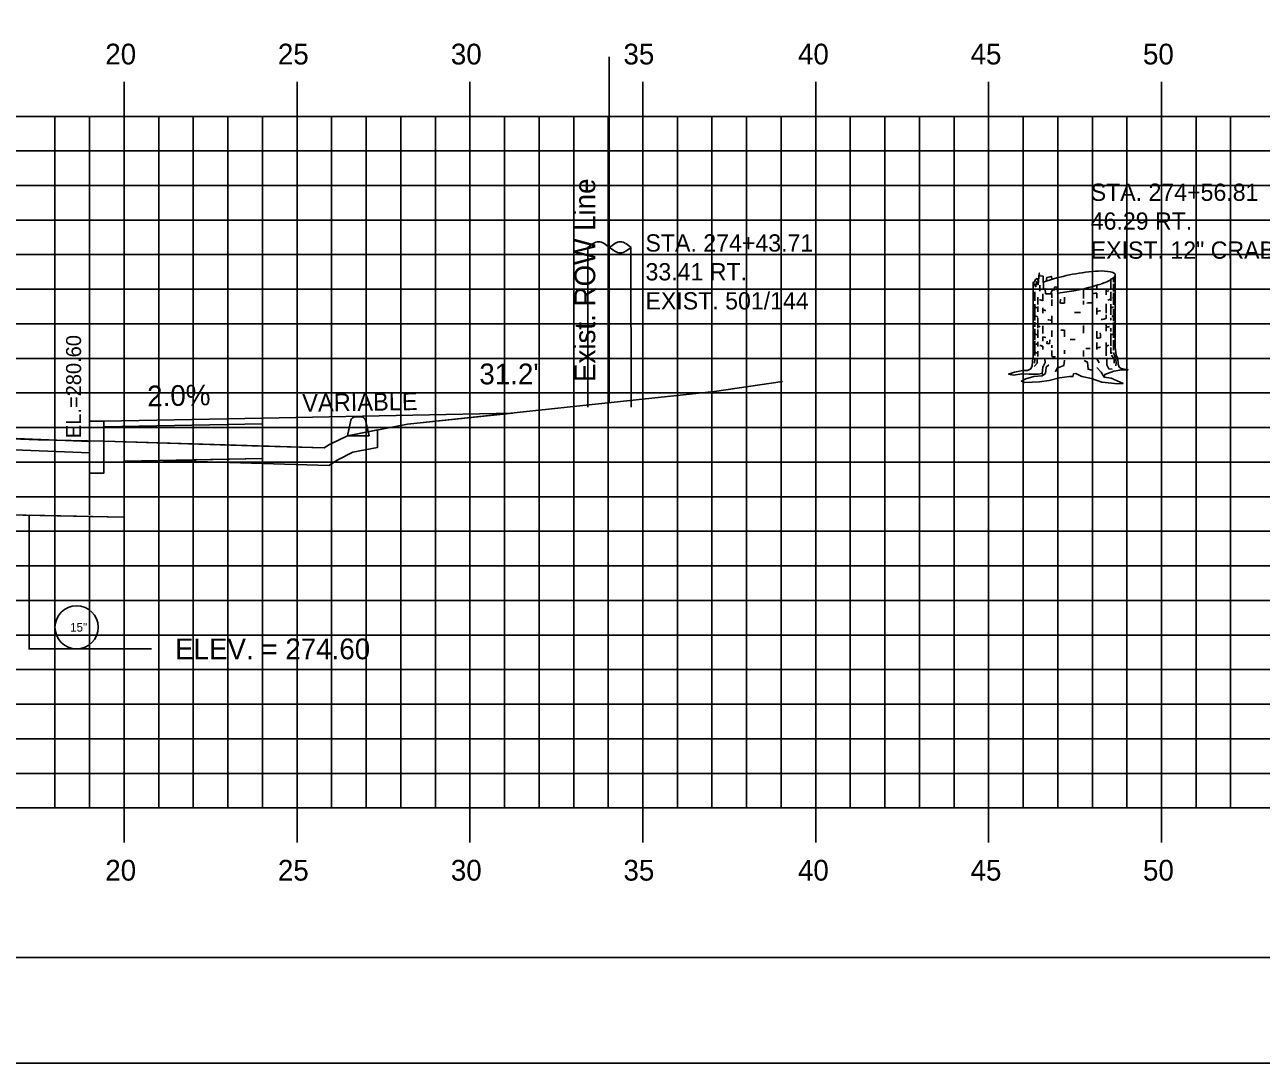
# Model space of a CAD drawing. Extents: x 853340 to 853510, y 366268 to 366378.
# Drawn here: x 853440.22 to 853475.99, y 366268.18 to 366298.21 of the extents above; entities that cross this region are included whole.
import ezdxf

# ---------------------------------------------------------------- set-up
doc = ezdxf.new("R2010")
doc.units = 0
for name, color, linetype in [('ANNOTATION', 7, 'Continuous'), ('BORDER', 7, 'Continuous'), ('D_Curb_Type_1_Rt', 7, 'Continuous'), ('D_Roadway_Edge_TW', 7, 'Continuous'), ('D_Roadway_FinishedGrade', 7, 'Continuous'), ('D_Roadway_Sidewalks_Paved', 7, 'Continuous'), ('D_Roadway_SubGrade', 7, 'Continuous'), ('D_Text_Monospaced', 7, 'Continuous'), ('D_Text_Standard', 7, 'Continuous'), ('E_ROW_Line', 7, 'Continuous'), ('H_V ANNOTATION', 7, 'Continuous'), ('JUNK COM EXC', 7, 'Continuous'), ('JUNK FILL', 7, 'Continuous'), ('junk grubnfill', 7, 'Continuous'), ('junk strct exc', 7, 'Continuous'), ('MAJOR', 7, 'Continuous'), ('MINOR', 7, 'Continuous'), ('PDRAIN', 7, 'Continuous'), ('PLOT BOUNDARY', 7, 'Continuous'), ('S_Curb_Type_3', 7, 'Continuous'), ('S_Roadway_Centerline', 7, 'Continuous'), ('S_Trees_Decid_Pay', 7, 'Continuous'), ('S_Utilities_Pole_Power', 7, 'Continuous')]:
    doc.layers.add(name, color=color, linetype=linetype)

msp = doc.modelspace()

# ---------------------------------------------------------------- linework, layer by layer
at = {"layer": 'BORDER'}
msp.add_line((853348.1, 366271.236), (853508.1, 366271.236), dxfattribs=at)
at = {"layer": 'D_Curb_Type_1_Rt'}
msp.add_lwpolyline([(853442.517, 366286.744), (853442.517, 366285.244), (853442.1, 366285.244), (853442.1, 366286.744)], close=True, dxfattribs=at)
at = {"layer": 'D_Roadway_Edge_TW'}
msp.add_lwpolyline([(853404.1, 366286.267), (853412.1, 366286.587), (853423.1, 366286.701), (853434.1, 366286.48), (853442.1, 366286.16)], dxfattribs=at)
at = {"layer": 'D_Roadway_FinishedGrade'}
msp.add_line((853447.105, 366286.835), (853454.338, 366286.979), dxfattribs=at)
at = {"layer": 'D_Roadway_Sidewalks_Paved'}
msp.add_lwpolyline([(853442.517, 366286.744), (853447.105, 366286.835), (853447.105, 366286.669), (853442.517, 366286.577)], close=True, dxfattribs=at)
at = {"layer": 'D_Roadway_SubGrade'}
msp.add_line((853450.424, 366286.489), (853450.424, 366285.98), dxfattribs=at)
for points in [[(853442.516, 366286.577), (853447.105, 366286.669), (853447.105, 366285.669), (853443.1, 366285.588), (853443.1, 366283.968)], [(853443.1, 366283.968), (853434.108, 366284.148), (853434.108, 366286.148), (853442.1, 366285.828)], [(853444.225, 366285.611), (853449.017, 366285.467), (853449.284, 366285.631), (853449.718, 366285.846), (853450.424, 366285.98)]]:
    msp.add_lwpolyline(points, dxfattribs=at)
at = {"layer": 'D_Text_Standard'}
msp.add_lwpolyline([(853443.1, 366280.159), (853443.212, 366280.159), (853443.892, 366280.159)], dxfattribs=at)
at = {"layer": 'E_ROW_Line'}
msp.add_line((853457.124, 366287.276), (853457.124, 366297.276), dxfattribs=at)
at = {"layer": 'JUNK COM EXC'}
msp.add_lwpolyline([(853403.1, 366285.982), (853403.1, 366284.074), (853412.108, 366284.254), (853423.108, 366284.368), (853443.1, 366283.968), (853443.1, 366285.588), (853447.105, 366285.669), (853447.105, 366286.025), (853442.522, 366286.163), (853440.609, 366286.208), (853435.982, 366286.375), (853424.096, 366286.691), (853423.104, 366286.714), (853422.159, 366286.693), (853411.503, 366286.496), (853410.582, 366286.432), (853404.575, 366286.053), (853403.1, 366285.982)], dxfattribs=at)
at = {"layer": 'JUNK FILL'}
msp.add_lwpolyline([(853447.105, 366286.025), (853448.883, 366285.971), (853449.042, 366286.069), (853449.557, 366286.324), (853451.29, 366286.654), (853454.338, 366286.979), (853447.105, 366286.835), (853447.105, 366286.669), (853447.105, 366286.025)], dxfattribs=at)
at = {"layer": 'junk grubnfill'}
msp.add_lwpolyline([(853447.105, 366286.025), (853447.105, 366285.669), (853444.225, 366285.611), (853449.017, 366285.467), (853449.284, 366285.631), (853449.718, 366285.846), (853450.424, 366285.98), (853450.424, 366286.489), (853449.557, 366286.324), (853449.042, 366286.069), (853448.883, 366285.971), (853447.105, 366286.025)], dxfattribs=at)
at = {"layer": 'junk strct exc'}
msp.add_lwpolyline([(853440.35, 366284.023), (853440.35, 366280.159), (853443.1, 366280.159), (853443.1, 366283.968)], close=True, dxfattribs=at)
at = {"layer": 'MAJOR'}
for p, q in [((853443.1, 366296.561), (853443.1, 366295.559)), ((853448.1, 366296.561), (853448.1, 366295.559)), ((853453.1, 366296.561), (853453.1, 366295.559)), ((853458.1, 366296.561), (853458.1, 366295.559)), ((853463.1, 366296.561), (853463.1, 366295.559)), ((853468.1, 366296.561), (853468.1, 366295.559)), ((853473.1, 366296.561), (853473.1, 366295.559)), ((853353.1, 366295.559), (853493.1, 366295.559)), ((853353.1, 366295.559), (853493.1, 366295.559)), ((853443.1, 366275.559), (853443.1, 366295.559)), ((853448.1, 366275.559), (853448.1, 366295.559)), ((853453.1, 366275.559), (853453.1, 366295.559)), ((853458.1, 366275.559), (853458.1, 366295.559)), ((853463.1, 366275.559), (853463.1, 366295.559)), ((853468.1, 366275.559), (853468.1, 366295.559)), ((853473.1, 366275.559), (853473.1, 366295.559)), ((853353.1, 366290.559), (853493.1, 366290.559)), ((853353.1, 366285.559), (853493.1, 366285.559)), ((853353.1, 366280.559), (853493.1, 366280.559)), ((853353.1, 366275.559), (853493.1, 366275.559)), ((853353.1, 366275.559), (853493.1, 366275.559)), ((853443.1, 366274.557), (853443.1, 366275.559)), ((853448.1, 366274.557), (853448.1, 366275.559)), ((853453.1, 366274.557), (853453.1, 366275.559)), ((853458.1, 366274.557), (853458.1, 366275.559)), ((853463.1, 366274.557), (853463.1, 366275.559)), ((853468.1, 366274.557), (853468.1, 366275.559)), ((853473.1, 366274.557), (853473.1, 366275.559))]:
    msp.add_line(p, q, dxfattribs=at)
at = {"layer": 'MINOR'}
for p, q in [((853441.1, 366275.559), (853441.1, 366295.559)), ((853442.1, 366284.032), (853442.1, 366295.559)), ((853444.1, 366275.559), (853444.1, 366295.559)), ((853445.1, 366275.559), (853445.1, 366295.559)), ((853446.1, 366275.559), (853446.1, 366295.559)), ((853447.1, 366275.559), (853447.1, 366295.559)), ((853449.1, 366275.559), (853449.1, 366295.559)), ((853450.1, 366275.559), (853450.1, 366295.559)), ((853451.1, 366275.559), (853451.1, 366295.559)), ((853452.1, 366275.559), (853452.1, 366295.559)), ((853454.1, 366275.559), (853454.1, 366295.559)), ((853455.1, 366275.559), (853455.1, 366295.559)), ((853456.1, 366275.559), (853456.1, 366295.559)), ((853457.1, 366275.559), (853457.1, 366295.559)), ((853459.1, 366275.559), (853459.1, 366295.559)), ((853460.1, 366275.559), (853460.1, 366295.559)), ((853461.1, 366275.559), (853461.1, 366295.559)), ((853462.1, 366275.559), (853462.1, 366295.559)), ((853464.1, 366275.559), (853464.1, 366295.559)), ((853465.1, 366275.559), (853465.1, 366295.559)), ((853466.1, 366275.559), (853466.1, 366295.559)), ((853467.1, 366275.559), (853467.1, 366295.559)), ((853469.1, 366275.559), (853469.1, 366295.559)), ((853470.1, 366275.559), (853470.1, 366295.559)), ((853471.1, 366275.559), (853471.1, 366295.559)), ((853472.1, 366275.559), (853472.1, 366295.559)), ((853474.1, 366275.559), (853474.1, 366295.559)), ((853475.1, 366275.559), (853475.1, 366295.559)), ((853353.1, 366294.559), (853493.1, 366294.559)), ((853353.1, 366293.559), (853493.1, 366293.559)), ((853353.1, 366292.559), (853493.1, 366292.559)), ((853353.1, 366291.559), (853493.1, 366291.559)), ((853353.1, 366289.559), (853493.1, 366289.559)), ((853353.1, 366288.559), (853493.1, 366288.559)), ((853353.1, 366287.559), (853493.1, 366287.559)), ((853353.1, 366286.559), (853493.1, 366286.559)), ((853353.1, 366284.559), (853493.1, 366284.559)), ((853442.1, 366275.559), (853442.1, 366283.988)), ((853353.1, 366283.559), (853493.1, 366283.559)), ((853353.1, 366282.559), (853493.1, 366282.559)), ((853353.1, 366281.559), (853493.1, 366281.559)), ((853353.1, 366279.559), (853493.1, 366279.559)), ((853353.1, 366278.559), (853493.1, 366278.559)), ((853353.1, 366277.559), (853493.1, 366277.559)), ((853353.1, 366276.559), (853493.1, 366276.559))]:
    msp.add_line(p, q, dxfattribs=at)
at = {"layer": 'PDRAIN'}
msp.add_lwpolyline([(853440.35, 366284.023), (853440.35, 366280.159), (853443.1, 366280.159), (853443.1, 366283.968)], dxfattribs=at)
msp.add_circle((853441.725, 366280.784), 0.625, dxfattribs=at)
at = {"layer": 'PLOT BOUNDARY'}
msp.add_lwpolyline([(853340.007, 366268.177), (853510.007, 366268.177), (853510.007, 366378.177), (853340.007, 366378.177)], close=True, dxfattribs=at)
at = {"layer": 'S_Curb_Type_3'}
for points in [[(853450.079, 366286.769), (853450.182, 366286.324), (853449.557, 366286.324), (853449.66, 366286.769)], [(853449.781, 366286.866), (853449.957, 366286.866)]]:
    msp.add_lwpolyline(points, dxfattribs=at)
for centre, start, end in [((853449.781, 366286.741), 90, 167.0054), ((853449.957, 366286.741), 12.9946, 90)]:
    msp.add_arc(centre, 0.125, start, end, dxfattribs=at)
at = {"layer": 'S_Roadway_Centerline'}
msp.add_lwpolyline([(853378.002, 366284.035), (853391.663, 366284.218), (853393.728, 366284.501), (853401.276, 366285.894), (853404.575, 366286.053), (853410.582, 366286.432), (853411.503, 366286.496), (853422.159, 366286.693), (853423.104, 366286.714), (853424.096, 366286.691), (853435.982, 366286.375), (853440.609, 366286.208), (853442.522, 366286.163), (853448.883, 366285.971), (853449.042, 366286.069), (853449.557, 366286.324), (853451.29, 366286.654), (853460.175, 366287.602), (853462.142, 366287.892)], dxfattribs=at)
at = {"layer": 'S_Trees_Decid_Pay'}
for p, q in [((853469.586, 366290.68), (853469.586, 366290.505)), ((853471.226, 366290.672), (853471.226, 366290.585)), ((853471.631, 366290.839), (853471.631, 366290.585)), ((853471.711, 366290.883), (853471.711, 366290.762)), ((853471.711, 366290.711), (853471.711, 366290.497)), ((853469.437, 366290.48), (853469.437, 366290.225)), ((853469.523, 366290.334), (853469.523, 366290.122)), ((853469.671, 366290.431), (853469.671, 366290.226)), ((853469.932, 366290.433), (853469.932, 366290.314)), ((853469.932, 366290.262), (853469.932, 366290.077)), ((853470.17, 366290.161), (853470.176, 366290.268)), ((853470.297, 366290.334), (853470.297, 366290.154)), ((853470.843, 366290.571), (853470.843, 366290.291)), ((853471.226, 366290.444), (853471.226, 366290.305)), ((853471.498, 366290.585), (853471.498, 366290.394)), ((853471.631, 366290.489), (853471.631, 366290.225)), ((853471.711, 366290.451), (853471.711, 366290.113)), ((853469.437, 366290.128), (853469.437, 366289.659)), ((853469.523, 366290.056), (853469.523, 366289.908)), ((853469.671, 366290.019), (853469.671, 366289.865)), ((853470.843, 366290.225), (853470.843, 366290.122)), ((853471.226, 366290.019), (853471.226, 366289.827)), ((853471.498, 366290.142), (853471.498, 366289.865)), ((853471.631, 366290.128), (853471.631, 366289.819)), ((853471.711, 366289.997), (853471.711, 366289.636)), ((853469.437, 366289.608), (853469.437, 366289.474)), ((853469.523, 366289.731), (853469.523, 366289.43)), ((853469.932, 366289.791), (853469.932, 366289.562)), ((853471.498, 366289.819), (853471.498, 366289.711)), ((853471.498, 366289.576), (853471.498, 366289.348)), ((853471.631, 366289.731), (853471.631, 366289.665)), ((853471.711, 366289.599), (853471.711, 366289.15)), ((853469.437, 366289.416), (853469.437, 366289.09)), ((853469.523, 366289.393), (853469.523, 366289.15)), ((853469.671, 366289.502), (853469.671, 366289.282)), ((853469.671, 366289.182), (853469.671, 366289.062)), ((853469.932, 366289.364), (853469.932, 366289.179)), ((853470.297, 366289.376), (853470.297, 366289.179)), ((853470.843, 366289.51), (853470.843, 366289.29)), ((853471.226, 366289.348), (853471.226, 366289.14)), ((853471.631, 366289.43), (853471.631, 366289.333)), ((853471.631, 366289.282), (853471.631, 366288.922)), ((853469.437, 366289.062), (853469.437, 366288.642)), ((853469.523, 366289.039), (853469.523, 366288.899)), ((853469.671, 366288.911), (853469.671, 366288.812)), ((853469.932, 366288.944), (853469.932, 366288.867)), ((853471.226, 366289.018), (853471.226, 366288.819)), ((853471.498, 366289.018), (853471.498, 366288.635)), ((853471.631, 366288.87), (853471.631, 366288.703)), ((853471.711, 366289.085), (853471.711, 366288.802)), ((853469.44, 366288.539), (853469.426, 366288.421)), ((853469.523, 366288.767), (853469.523, 366288.611)), ((853469.932, 366288.79), (853469.932, 366288.617)), ((853470.297, 366288.796), (853470.297, 366288.693)), ((853470.843, 366288.79), (853470.843, 366288.617)), ((853471.222, 366288.562), (853471.302, 366288.43))]:
    msp.add_line(p, q, dxfattribs=at)
for points in [[(853469.386, 366290.754), (853469.386, 366288.617), (853469.366, 366288.475), (853469.36, 366288.349), (853469.317, 366288.262), (853469.224, 366288.213), (853469.088, 366288.213), (853468.845, 366288.157), (853468.678, 366288.108), (853468.821, 366288.077), (853469.058, 366288.115), (853469.268, 366288.102), (853469.529, 366288.108), (853469.653, 366288.127), (853469.683, 366288.084), (853469.745, 366288.127), (853469.646, 366288.059), (853469.411, 366288.034), (853469.181, 366287.972), (853469.051, 366287.902), (853469.15, 366287.859), (853469.572, 366287.878), (853469.85, 366287.921), (853470.149, 366287.997), (853470.435, 366288.034), (853470.54, 366288.034), (853470.558, 366288.115), (853470.626, 366288.121), (853470.793, 366288.034), (853471.079, 366287.978), (853471.378, 366287.871), (853471.837, 366287.822), (853471.991, 366287.835), (853471.649, 366287.985), (853471.446, 366288.016), (853471.458, 366288.09), (853471.718, 366288.189), (853471.893, 366288.22), (853472.134, 366288.232), (853471.936, 366288.269), (853471.874, 366288.306), (853471.85, 366288.392), (853471.837, 366288.562), (853471.792, 366288.648), (853471.764, 366288.888), (853471.764, 366290.974)], [(853469.743, 366290.426), (853469.735, 366290.571), (853469.689, 366290.563), (853469.675, 366290.938), (853469.581, 366290.945), (853469.566, 366291.026), (853469.529, 366290.688), (853469.483, 366290.783), (853469.463, 366290.629), (853469.386, 366290.754), (853469.392, 366290.564)], [(853469.386, 366290.754), (853469.432, 366290.777), (853469.455, 366290.842), (853469.506, 366290.865), (853469.54, 366290.791)], [(853469.765, 366290.793), (853469.786, 366290.9), (853469.918, 366290.931), (853469.925, 366290.843)], [(853469.904, 366290.431), (853469.941, 366290.534), (853470.006, 366290.54), (853470.006, 366290.622), (853470.081, 366290.629), (853470.105, 366290.448)], [(853471.34, 366289.153), (853471.338, 366289.23), (853471.331, 366289.297)], [(853469.794, 366289.062), (853469.786, 366288.987), (853469.86, 366288.982), (853469.874, 366289.098)], [(853469.506, 366288.547), (853469.5, 366288.421), (853469.418, 366288.327)], [(853469.653, 366288.127), (853469.671, 366288.306), (853469.733, 366288.442), (853469.726, 366288.543)], [(853470.295, 366288.51), (853470.278, 366288.356), (853470.081, 366288.275), (853470.035, 366288.172)], [(853470.861, 366288.501), (853470.964, 366288.45), (853470.978, 366288.244), (853471.081, 366288.215)], [(853471.516, 366288.575), (853471.516, 366288.37), (853471.573, 366288.26), (853471.67, 366288.244)], [(853471.656, 366288.65), (853471.727, 366288.547), (853471.727, 366288.421)], [(853471.713, 366288.73), (853471.773, 366288.569), (853471.787, 366288.444), (853471.779, 366288.347)], [(853469.844, 366288.374), (853469.769, 366288.306), (853469.751, 366288.207), (853469.745, 366288.127)], [(853471.446, 366288.016), (853471.359, 366288.157), (853471.228, 366288.3)]]:
    msp.add_lwpolyline(points, dxfattribs=at)
for centre, radius, start, end in [((853471.676, 366284.973), 6.126, 100.7779, 107.8613), ((853471.676, 366284.973), 6.126, 93.6944, 100.7779), ((853471.365, 366289.789), 1.299, 78.2779, 93.6944), ((853471.532, 366290.592), 0.48, 69.9843, 78.2779), ((853471.64, 366290.888), 0.164, 55.7779, 69.9843), ((853471.672, 366290.935), 0.107, 45.9547, 55.7779), ((853471.701, 366290.966), 0.0645, 33.2779, 45.9547), ((853471.71, 366290.972), 0.0544, 22.46, 33.2779), ((853471.699, 366290.977), 0.0645, 335.6011, 348.2779), ((853471.717, 366290.975), 0.0467, 10.7779, 22.46), ((853471.717, 366290.975), 0.0467, 359.0957, 10.7779), ((853471.709, 366290.975), 0.0544, 348.2779, 359.0957), ((853470.196, 366289.567), 1.299, 107.8613, 113.3069), ((853469.474, 366296.541), 6.126, 280.7779, 287.8613), ((853470.954, 366291.948), 1.299, 287.8613, 303.2779), ((853471.404, 366291.262), 0.48, 303.2779, 311.5714), ((853471.614, 366291.026), 0.164, 311.5714, 325.7779), ((853471.665, 366290.677), 0.109, 315, 324.8263), ((853471.661, 366290.994), 0.107, 325.7779, 335.6011), ((853471.7, 366290.652), 0.0657, 324.8263, 337.5), ((853471.709, 366290.648), 0.0554, 337.5, 348.3185), ((853469.434, 366290.386), 0.0476, 180, 191.6815), ((853469.442, 366290.387), 0.0554, 191.6815, 202.5), ((853469.451, 366290.391), 0.0657, 202.5, 215.1737), ((853469.487, 366290.416), 0.109, 215.1737, 225), ((853469.527, 366290.457), 0.166, 225, 239.1924), ((853469.999, 366291.476), 1.292, 250.6119, 255.2856), ((853469.785, 366291.725), 1.299, 268.1289, 273.6944), ((853469.474, 366296.541), 6.126, 273.6944, 274.0246), ((853469.474, 366296.541), 6.126, 275.9147, 280.7779), ((853470.576, 366296.325), 5.916, 274.9515, 276.3087), ((853471.152, 366291.737), 1.292, 285.5651, 289.0916), ((853471.151, 366291.476), 1.292, 288.0829, 292.5), ((853471.46, 366290.73), 0.484, 297.4162, 300.8076), ((853471.623, 366290.457), 0.166, 300.8076, 315), ((853471.624, 366290.717), 0.166, 301.67, 315), ((853471.664, 366290.416), 0.109, 315, 324.8263), ((853471.699, 366290.391), 0.0657, 324.8263, 337.5), ((853471.708, 366290.387), 0.0554, 337.5, 348.3185), ((853469.527, 366290.193), 0.166, 237.0378, 239.1924), ((853469.69, 366290.466), 0.484, 239.1924, 247.5), ((853469.999, 366291.212), 1.292, 247.5, 248.3537), ((853469.999, 366291.212), 1.292, 255.2856, 259.2632), ((853470.575, 366296.064), 5.916, 266.0776, 267.3043), ((853470.575, 366295.8), 5.916, 270.1162, 271.7708), ((853470.575, 366296.064), 5.916, 273.5382, 274.8924), ((853470.575, 366295.8), 5.916, 276.3184, 277.1546), ((853471.151, 366291.212), 1.292, 277.1546, 278.3662), ((853471.151, 366291.212), 1.292, 291.8071, 292.5), ((853471.46, 366290.466), 0.484, 292.5, 300.8076), ((853471.623, 366290.193), 0.166, 300.8076, 301.6001), ((853469.434, 366289.865), 0.0476, 180, 191.6815), ((853469.434, 366289.607), 0.0476, 180, 191.6815), ((853469.442, 366289.866), 0.0554, 191.6815, 202.5), ((853469.442, 366289.609), 0.0554, 191.6815, 202.5), ((853469.451, 366289.87), 0.0657, 202.5, 215.1737), ((853469.451, 366289.613), 0.0657, 202.5, 215.1737), ((853469.487, 366289.895), 0.109, 215.1737, 225), ((853469.487, 366289.638), 0.109, 215.1737, 225), ((853469.527, 366289.936), 0.166, 225, 239.1924), ((853469.527, 366289.678), 0.166, 225, 239.1924), ((853469.69, 366290.209), 0.484, 239.1924, 245.7725), ((853469.999, 366290.955), 1.292, 247.5, 248.4842), ((853469.999, 366290.955), 1.292, 261.8726, 262.8454), ((853470.575, 366295.543), 5.916, 262.8454, 263.7595), ((853471.151, 366290.955), 1.292, 279.2565, 285.6105), ((853471.46, 366290.209), 0.484, 294.6372, 300.8076), ((853471.623, 366289.936), 0.166, 300.8076, 315), ((853471.623, 366289.678), 0.166, 302.0694, 315), ((853471.664, 366289.895), 0.109, 315, 324.8263), ((853471.664, 366289.638), 0.109, 315, 324.8263), ((853471.699, 366289.87), 0.0657, 324.8263, 337.5), ((853471.699, 366289.613), 0.0657, 324.8263, 337.5), ((853471.708, 366289.866), 0.0554, 337.5, 348.3185), ((853471.708, 366289.609), 0.0554, 337.5, 348.3185), ((853469.434, 366289.342), 0.0476, 180, 191.6815), ((853469.442, 366289.343), 0.0554, 191.6815, 202.5), ((853469.451, 366289.347), 0.0657, 202.5, 215.1737), ((853469.487, 366289.372), 0.109, 215.1737, 225), ((853469.527, 366289.413), 0.166, 225, 239.1924), ((853469.69, 366289.686), 0.484, 239.1924, 247.5), ((853469.999, 366290.698), 1.292, 247.5, 251.799), ((853469.999, 366290.432), 1.292, 247.5, 248.3537), ((853469.999, 366290.432), 1.292, 255.2856, 259.2463), ((853470.575, 366295.285), 5.916, 266.2721, 267.3043), ((853471.151, 366290.698), 1.292, 285.6105, 290.1001), ((853471.46, 366289.686), 0.484, 292.5, 300.8076), ((853471.623, 366289.413), 0.166, 300.8076, 302.0694), ((853471.708, 366289.343), 0.0554, 337.5, 348.3185), ((853469.69, 366289.414), 0.484, 242.734, 247.5), ((853469.999, 366290.16), 1.292, 251.3664, 255.2856), ((853470.575, 366295.02), 5.916, 268.9207, 270), ((853470.575, 366295.02), 5.916, 270, 270.2757), ((853470.575, 366294.748), 5.916, 273.2637, 274.461), ((853470.575, 366295.02), 5.916, 276.3184, 277.1546), ((853470.575, 366294.748), 5.916, 276.3184, 277.1546), ((853471.151, 366290.432), 1.292, 277.1546, 278.3795), ((853471.151, 366290.16), 1.292, 277.1546, 278.3662), ((853471.151, 366290.16), 1.292, 285.6105, 289.1534), ((853471.623, 366289.141), 0.166, 302.0694, 315), ((853471.664, 366289.1), 0.109, 315, 324.8263), ((853471.699, 366289.075), 0.0657, 324.8263, 337.5), ((853471.708, 366289.071), 0.0554, 337.5, 348.3185), ((853469.434, 366288.812), 0.0476, 180, 191.6815), ((853469.442, 366288.814), 0.0554, 191.6815, 202.5), ((853469.451, 366288.818), 0.0657, 202.5, 215.1737), ((853469.487, 366288.843), 0.109, 215.1737, 225), ((853469.527, 366288.884), 0.166, 225, 239.1924), ((853469.69, 366289.156), 0.484, 239.1924, 247.5), ((853469.999, 366289.903), 1.292, 247.5, 248.3537), ((853470.575, 366294.491), 5.916, 263.7831, 264.7656), ((853471.16, 366289.907), 1.292, 291.3696, 292.0604), ((853471.46, 366289.156), 0.484, 292.5, 296.5499)]:
    msp.add_arc(centre, radius, start, end, dxfattribs=at)
at = {"layer": 'S_Utilities_Pole_Power'}
for p, q in [((853456.51, 366287.15), (853456.507, 366291.77)), ((853456.51, 366291.77), (853456.666, 366291.88)), ((853456.978, 366291.88), (853457.135, 366291.77)), ((853457.291, 366291.88), (853457.135, 366291.77)), ((853457.135, 366291.77), (853457.291, 366291.659)), ((853457.76, 366291.77), (853457.604, 366291.88)), ((853457.604, 366291.659), (853457.76, 366291.77)), ((853457.76, 366287.15), (853457.757, 366291.77))]:
    msp.add_line(p, q, dxfattribs=at)
for centre, start, end in [((853456.822, 366291.659), 90, 125.2644), ((853456.822, 366291.659), 54.7356, 90), ((853457.447, 366291.659), 90, 125.2644), ((853457.447, 366291.659), 54.7356, 90), ((853457.447, 366291.88), 234.7356, 270), ((853457.447, 366291.88), 270, 305.2644)]:
    msp.add_arc(centre, 0.271, start, end, dxfattribs=at)

# ---------------------------------------------------------------- texts
at = {"layer": 'ANNOTATION'}
msp.add_text('2.0%', height=0.6, rotation=1.1363, dxfattribs=at).set_placement((853443.773, 366287.169))
at = {"layer": 'D_Text_Monospaced'}
for s, height, p in [('STA. 274+56.81', 0.49998, (853471.053, 366293.115)), ('46.29 RT.', 0.5, (853471.053, 366292.281)), ('STA. 274+43.71', 0.49998, (853458.177, 366291.648)), ('EXIST. 12" CRAB APPLE', 0.49998, (853471.053, 366291.441)), ('33.41 RT.', 0.5, (853458.177, 366290.814)), ('EXIST. 501/144', 0.49998, (853458.177, 366289.974))]:
    msp.add_text(s, height=height, dxfattribs=at).set_placement(p)
at = {"layer": 'D_Text_Standard'}
for s, height, rotation, p in [(' EL.=280.60', 0.4335, 90, (853441.854, 366286.092)), ('VARIABLE', 0.51, 0.856, (853448.255, 366287.016))]:
    msp.add_text(s, height=height, rotation=rotation, dxfattribs=at).set_placement(p)
for s, p in [("31.2'", (853453.372, 366287.809)), ('ELEV. = 274.60', (853444.572, 366279.859))]:
    msp.add_text(s, height=0.6, dxfattribs=at).set_placement(p)
at = {"layer": 'E_ROW_Line'}
msp.add_text('Exist. ROW Line', height=0.6, rotation=90, dxfattribs=at).set_placement((853456.724, 366287.876))
at = {"layer": 'H_V ANNOTATION'}
for s, p in [('20', (853442.554, 366297.059)), ('25', (853447.546, 366297.059)), ('30', (853452.548, 366297.059)), ('35', (853457.54, 366297.059)), ('40', (853462.586, 366297.059)), ('45', (853467.578, 366297.059)), ('50', (853472.564, 366297.059)), ('20', (853442.554, 366273.459)), ('25', (853447.546, 366273.459)), ('30', (853452.548, 366273.459)), ('35', (853457.54, 366273.459)), ('40', (853462.586, 366273.459)), ('45', (853467.578, 366273.459)), ('50', (853472.564, 366273.459))]:
    msp.add_text(s, height=0.6, dxfattribs=at).set_placement(p)
at = {"layer": 'PDRAIN'}
msp.add_text('15"', height=0.25, dxfattribs=at).set_placement((853441.538, 366280.659))

doc.saveas('drawing.dxf')
